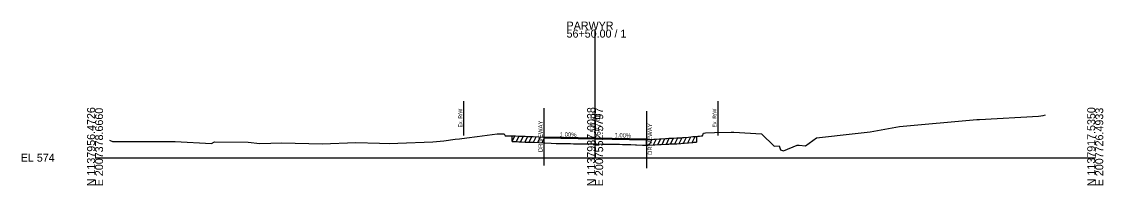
# Model space of a CAD drawing. Extents: x -2173 to 2007764, y -181 to 1138563.
# Drawn here: x 1017.4 to 1395.9, y 1990.3 to 2047.6 of the extents above; entities that cross this region are included whole.
import ezdxf

# ---------------------------------------------------------------- set-up
doc = ezdxf.new("R2010")
doc.units = 0
for name, color, linetype in [('Default', 7, 'Continuous'), ('RD_PD_Final_TrvlWay', 7, 'Continuous'), ('RD_PD_MedBWall', 7, 'Continuous'), ('RD_XS_ExPaveRet', 7, 'Continuous'), ('RD_XS_ExRW', 7, 'Continuous'), ('RD_XS_GR', 7, 'Continuous'), ('RD_XS_MedBWall', 7, 'Continuous'), ('RD_XS_SideStreet', 7, 'Continuous'), ('RD_XS_TX_Elev_EX', 7, 'Continuous'), ('RD_XS_TX_Elev_PR', 7, 'Continuous')]:
    doc.layers.add(name, color=color, linetype=linetype)

msp = doc.modelspace()

# ---------------------------------------------------------------- linework, layer by layer
at = {"layer": 'RD_PD_Final_TrvlWay'}
msp.add_lwpolyline([(1048.14, 2006.19), (1049.16, 2005.65), (1071.19, 2005.62), (1083.79, 2004.94), (1084.92, 2005.52), (1096.71, 2005.41), (1100.78, 2004.96), (1108.49, 2005.25), (1122.61, 2004.8), (1134.4, 2005.32), (1142.67, 2005.11), (1146.02, 2004.98), (1149.09, 2005.05), (1161.31, 2005.6), (1165.19, 2005.93), (1169.11, 2006.43), (1170.67, 2006.6), (1173.21, 2006.91), (1176.81, 2007.38), (1183.8, 2008.41), (1184.66, 2008.39), (1185.66, 2008.41), (1186.3, 2008.4), (1186.61, 2007.63), (1187.24, 2007.65), (1189.01, 2007.7), (1190.23, 2007.62), (1191.38, 2007.53), (1192.36, 2007.5), (1193.65, 2007.48), (1194.37, 2007.45), (1195.91, 2007.42), (1196.39, 2007.41), (1198.4, 2007.31), (1200.44, 2007.24), (1202.71, 2007.05), (1204.44, 2006.99), (1204.98, 2006.99), (1206.45, 2006.99), (1207.24, 2006.99), (1208.46, 2006.98), (1209.51, 2006.93), (1210.47, 2006.88), (1211.77, 2006.87), (1212.49, 2006.85), (1214.04, 2006.85), (1214.5, 2006.85), (1216.51, 2006.85), (1218.14, 2006.83), (1218.57, 2006.82), (1220.54, 2006.79), (1220.84, 2006.78), (1222.55, 2006.73), (1223.11, 2006.72), (1224.56, 2006.71), (1225.37, 2006.71), (1226.57, 2006.68), (1227.64, 2006.65), (1228.59, 2006.65), (1229.9, 2006.63), (1230.6, 2006.6), (1232.17, 2006.51), (1232.61, 2006.49), (1234.62, 2006.42), (1236.11, 2006.41), (1236.7, 2006.41), (1238.65, 2006.53), (1238.97, 2006.54), (1240.66, 2006.63), (1241.23, 2006.65), (1242.67, 2006.7), (1243.23, 2006.74), (1243.88, 2006.78), (1244.19, 2006.81), (1244.66, 2006.83), (1245.63, 2006.86), (1246.7, 2006.9), (1248.03, 2006.98), (1248.71, 2007.03), (1249.25, 2007.07), (1250.72, 2007.19), (1252.28, 2007.37), (1252.59, 2007.39), (1253.12, 2007.44), (1253.55, 2007.47), (1254.04, 2007.51), (1254.57, 2007.56), (1255.17, 2007.61), (1255.7, 2007.65), (1255.98, 2008.54), (1256.3, 2008.62), (1256.77, 2008.73), (1259.81, 2008.81), (1265.65, 2008.89), (1266.59, 2008.9), (1276.35, 2008.32), (1280.72, 2003.99), (1282.52, 2004.18), (1282.93, 2002.78), (1283.96, 2002.35), (1288.75, 2004.39), (1289.45, 2004.41), (1291.67, 2004.19), (1295.53, 2006.99), (1309.13, 2008.43), (1314.39, 2009.05), (1324.58, 2010.93), (1351.65, 2013.39), (1352.62, 2013.42), (1373.19, 2014.58), (1374.89, 2014.82), (1375.65, 2014.95)], dxfattribs=at)
at = {"layer": 'RD_PD_MedBWall'}
for p, q in [((1218.1, 2000), (1218.1, 2044.84)), ((1043.1, 2000), (1218.1, 2000)), ((1218.1, 2000), (1393.1, 2000))]:
    msp.add_line(p, q, dxfattribs=at)
at = {"layer": 'RD_XS_ExPaveRet'}
for p, q in [((1189.01, 2005.7), (1189.01, 2007.7)), ((1189.01, 2005.7), (1189.97, 2007.64)), ((1190.51, 2005.6), (1191.47, 2007.53)), ((1192.01, 2005.51), (1193, 2007.49)), ((1193.51, 2005.48), (1194.49, 2007.45)), ((1195.01, 2005.44), (1196, 2007.42)), ((1196.51, 2005.41), (1197.48, 2007.36)), ((1198.01, 2005.33), (1198.99, 2007.29)), ((1199.51, 2005.27), (1200.1, 2006.46)), ((1236.1, 2006.27), (1200.1, 2006.99)), ((1236.1, 2004.41), (1236.1, 2006.27)), ((1237.01, 2004.43), (1238.04, 2006.49)), ((1238.51, 2004.52), (1239.53, 2006.57)), ((1240.01, 2004.59), (1241.03, 2006.64)), ((1241.51, 2004.66), (1242.52, 2006.7)), ((1243.01, 2004.72), (1244.04, 2006.79)), ((1244.51, 2004.82), (1245.52, 2006.86)), ((1246.01, 2004.87), (1247.03, 2006.92)), ((1247.51, 2004.95), (1248.54, 2007.02)), ((1249.01, 2005.05), (1250.05, 2007.14)), ((1250.51, 2005.17), (1251.56, 2007.29)), ((1252.01, 2005.34), (1253.05, 2007.43)), ((1253.55, 2007.47), (1253.55, 2005.47)), ((1189.01, 2005.7), (1190.23, 2005.62)), ((1190.23, 2005.62), (1191.38, 2005.53)), ((1191.38, 2005.53), (1192.36, 2005.5)), ((1192.36, 2005.5), (1193.65, 2005.48)), ((1193.65, 2005.48), (1194.37, 2005.45)), ((1194.37, 2005.45), (1195.91, 2005.42)), ((1195.91, 2005.42), (1196.39, 2005.41)), ((1196.39, 2005.41), (1198.4, 2005.31)), ((1198.4, 2005.31), (1200.44, 2005.24)), ((1200.1, 2005.25), (1200.44, 2005.24)), ((1200.44, 2005.24), (1202.71, 2005.05)), ((1200.44, 2005.24), (1202.71, 2005.05)), ((1202.71, 2005.05), (1204.44, 2004.99)), ((1202.71, 2005.05), (1204.44, 2004.99)), ((1204.44, 2004.99), (1204.98, 2004.99)), ((1204.44, 2004.99), (1204.98, 2004.99)), ((1204.98, 2004.99), (1206.45, 2004.99)), ((1204.98, 2004.99), (1206.45, 2004.99)), ((1206.45, 2004.99), (1207.24, 2004.99)), ((1206.45, 2004.99), (1207.24, 2004.99)), ((1207.24, 2004.99), (1208.46, 2004.98)), ((1207.24, 2004.99), (1208.46, 2004.98)), ((1208.46, 2004.98), (1209.51, 2004.93)), ((1208.46, 2004.98), (1209.51, 2004.93)), ((1209.51, 2004.93), (1210.47, 2004.88)), ((1209.51, 2004.93), (1210.47, 2004.88)), ((1210.47, 2004.88), (1211.77, 2004.87)), ((1210.47, 2004.88), (1211.77, 2004.87)), ((1211.77, 2004.87), (1212.49, 2004.85)), ((1211.77, 2004.87), (1212.49, 2004.85)), ((1212.49, 2004.85), (1214.04, 2004.85)), ((1212.49, 2004.85), (1214.04, 2004.85)), ((1214.04, 2004.85), (1214.5, 2004.85)), ((1214.04, 2004.85), (1214.5, 2004.85)), ((1214.5, 2004.85), (1216.51, 2004.85)), ((1214.5, 2004.85), (1216.51, 2004.85)), ((1216.51, 2004.85), (1218.14, 2004.83)), ((1216.51, 2004.85), (1218.14, 2004.83)), ((1218.14, 2004.83), (1218.57, 2004.82)), ((1218.14, 2004.83), (1218.57, 2004.82)), ((1218.57, 2004.82), (1220.54, 2004.79)), ((1218.57, 2004.82), (1220.54, 2004.79)), ((1220.54, 2004.79), (1220.84, 2004.78)), ((1220.54, 2004.79), (1220.84, 2004.78)), ((1220.84, 2004.78), (1222.55, 2004.73)), ((1220.84, 2004.78), (1222.55, 2004.73)), ((1222.55, 2004.73), (1223.11, 2004.72)), ((1222.55, 2004.73), (1223.11, 2004.72)), ((1223.11, 2004.72), (1224.56, 2004.71)), ((1223.11, 2004.72), (1224.56, 2004.71)), ((1224.56, 2004.71), (1225.37, 2004.71)), ((1224.56, 2004.71), (1225.37, 2004.71)), ((1225.37, 2004.71), (1226.57, 2004.68)), ((1225.37, 2004.71), (1226.57, 2004.68)), ((1226.57, 2004.68), (1227.64, 2004.65)), ((1226.57, 2004.68), (1227.64, 2004.65)), ((1227.64, 2004.65), (1228.59, 2004.65)), ((1227.64, 2004.65), (1228.59, 2004.65)), ((1228.59, 2004.65), (1229.9, 2004.63)), ((1228.59, 2004.65), (1229.9, 2004.63)), ((1229.9, 2004.63), (1230.6, 2004.6)), ((1229.9, 2004.63), (1230.6, 2004.6)), ((1230.6, 2004.6), (1232.17, 2004.51)), ((1230.6, 2004.6), (1232.17, 2004.51)), ((1232.17, 2004.51), (1232.61, 2004.49)), ((1232.17, 2004.51), (1232.61, 2004.49)), ((1232.61, 2004.49), (1234.62, 2004.42)), ((1232.61, 2004.49), (1234.62, 2004.42)), ((1234.62, 2004.42), (1236.11, 2004.41)), ((1234.62, 2004.42), (1236.1, 2004.41)), ((1236.11, 2004.41), (1236.7, 2004.41)), ((1236.7, 2004.41), (1238.65, 2004.53)), ((1238.65, 2004.53), (1238.97, 2004.54)), ((1238.97, 2004.54), (1240.66, 2004.63)), ((1240.66, 2004.63), (1241.23, 2004.65)), ((1241.23, 2004.65), (1242.67, 2004.7)), ((1242.67, 2004.7), (1243.23, 2004.74)), ((1243.23, 2004.74), (1243.88, 2004.78)), ((1243.88, 2004.78), (1244.19, 2004.81)), ((1244.19, 2004.81), (1244.66, 2004.83)), ((1244.66, 2004.83), (1245.63, 2004.86)), ((1245.63, 2004.86), (1246.7, 2004.9)), ((1246.7, 2004.9), (1248.03, 2004.98)), ((1248.03, 2004.98), (1248.71, 2005.03)), ((1248.71, 2005.03), (1249.25, 2005.07)), ((1249.25, 2005.07), (1250.72, 2005.19)), ((1250.72, 2005.19), (1252.28, 2005.37)), ((1252.28, 2005.37), (1252.59, 2005.39)), ((1252.59, 2005.39), (1253.12, 2005.44)), ((1253.12, 2005.44), (1253.55, 2005.47))]:
    msp.add_line(p, q, dxfattribs=at)
msp.add_lwpolyline([(1200.1, 2006.99), (1200.1, 2006.46), (1200.1, 2005.25)], dxfattribs=at)
at = {"layer": 'RD_XS_ExRW'}
for p, q in [((1172.07, 2019.79), (1172.07, 2007.79)), ((1261.06, 2019.79), (1261.06, 2007.79))]:
    msp.add_line(p, q, dxfattribs=at)
at = {"layer": 'RD_XS_MedBWall'}
for p, q in [((1200.1, 2007.32), (1236.1, 2006.6)), ((1200.1, 2006.99), (1236.1, 2006.27))]:
    msp.add_line(p, q, dxfattribs=at)
at = {"layer": 'RD_XS_SideStreet'}
for p, q in [((1200.1, 2017.28), (1200.1, 1997.28)), ((1236.1, 2016.32), (1236.1, 1996.32))]:
    msp.add_line(p, q, dxfattribs=at)

# ---------------------------------------------------------------- texts
at = {"layer": 'Default'}
msp.add_text('-', height=0.0001, dxfattribs=at).set_placement((1043.1, 2000))
at = {"layer": 'RD_PD_MedBWall'}
for s, p in [('56+50.00 / 1', (1208.1, 2042.04)), ('PARWYR', (1208.1, 2044.84)), ('EL 574', (1017.1, 1998.6))]:
    msp.add_text(s, height=2.8, dxfattribs=at).set_placement(p)
for s, p in [('N 1137956.4726', (1043.1, 1990)), ('E 2007378.6660', (1045.9, 1990)), ('N 1137937.0038', (1218.1, 1990)), ('E 2007552.5797', (1220.9, 1990)), ('N 1137917.5350', (1393.1, 1990)), ('E 2007726.4933', (1395.9, 1990))]:
    msp.add_text(s, height=2.8, rotation=90, dxfattribs=at).set_placement(p)
at = {"layer": 'RD_XS_ExRW'}
for p in [(1171.57, 2010.56), (1260.56, 2010.56)]:
    msp.add_text('Ex. R/W ', height=1.3, rotation=90, dxfattribs=at).set_placement(p)
at = {"layer": 'RD_XS_GR'}
for p in [(1205.7, 2007.38), (1224.85, 2007.12)]:
    msp.add_text('1.00%', height=1.5, rotation=359.208, dxfattribs=at).set_placement(p)
at = {"layer": 'RD_XS_SideStreet'}
for p in [(1199.71, 2001.94), (1238.02, 2000.98)]:
    msp.add_text('DRIVEWAY', height=1.5, rotation=90, dxfattribs=at).set_placement(p)
at = {"layer": 'RD_XS_TX_Elev_EX'}
msp.add_text('577.41', height=1.6, rotation=90, dxfattribs=at).set_placement((1218, 2008.83))
at = {"layer": 'RD_XS_TX_Elev_PR'}
msp.add_text('577.48', height=1.8, rotation=90, dxfattribs=at).set_placement((1220, 2007.86))

doc.saveas('drawing.dxf')
